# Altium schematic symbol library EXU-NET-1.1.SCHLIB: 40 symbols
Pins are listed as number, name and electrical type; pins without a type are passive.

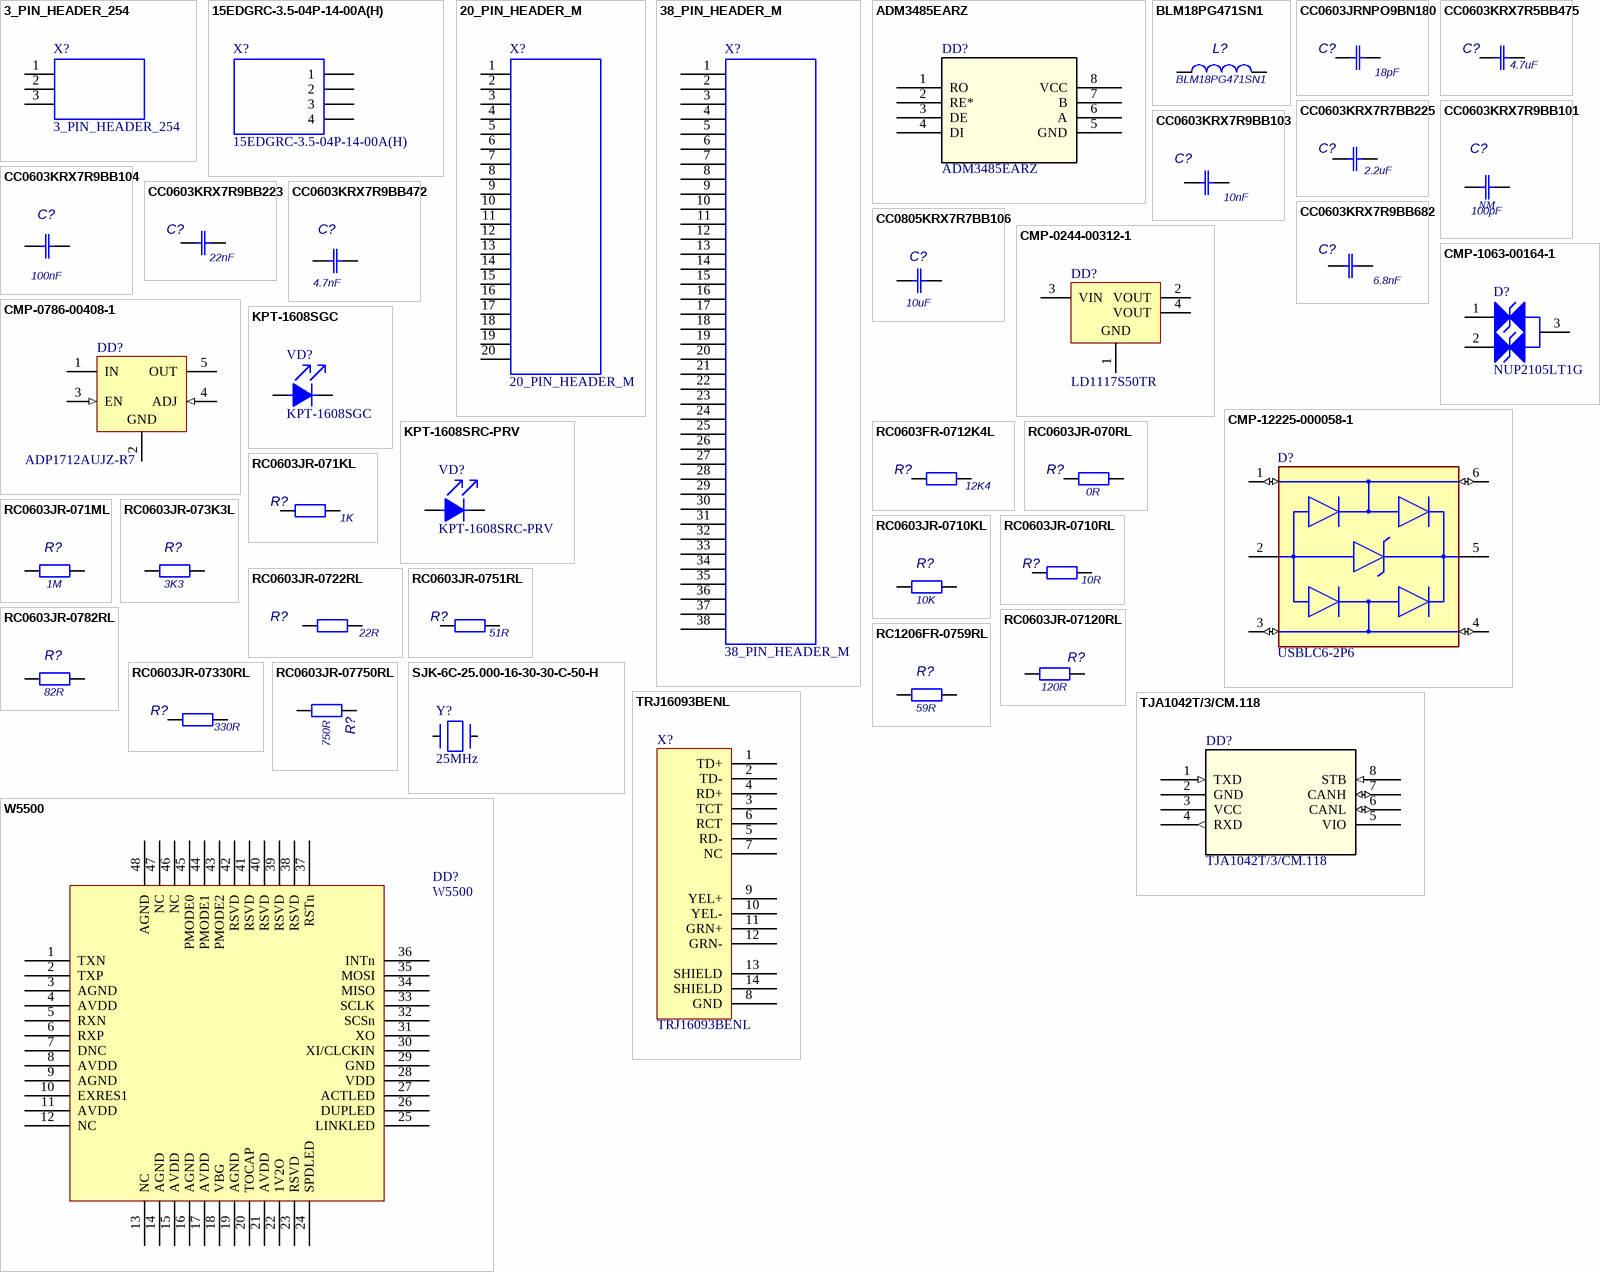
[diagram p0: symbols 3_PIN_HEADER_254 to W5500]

## 3_PIN_HEADER_254
designator X?
2,54mm Pitch, 1 Row, 3 Circuits, Vertical, THT
footprint 3_PIN_HEADER_254
pins: 1, 2, 3

## 15EDGRC-3.5-04P-14-00A(H)
designator X?
TERM BLOCK HDR 4POS 90DEG 3.5MM; Manufacturer: Degson Electronics
footprint 15EDGRC-3.5-04P-14-00A(H)
pins: 1, 2, 3, 4

## 20_PIN_HEADER_M
designator X?
footprint 20_PIN_HEADER_M
pins: 1, 2, 3, 4, 5, 6, 7, 8, 9, 10, 11, 12, 13, 14, 15, 16, 17, 18, 19, 20

## 38_PIN_HEADER_M
designator X?
footprint 38_PIN_HEADER_M
pins: 1, 2, 3, 4, 5, 6, 7, 8, 9, 10, 11, 12, 13, 14, 15, 16, 17, 18, 19, 20, 21, 22, 23, 24, 25, 26, 27, 28, 29, 30, 31, 32, 33, 34, 35, 36, 37, 38

## ADM3485EARZ
designator DD?
3.3 V, Â±15 kV ESD-Protected, RS-485/RS-422 Transceiver (Half Duplex, 12Mbps, DE/RE); Manufacturer: Youtai Semiconductor (UMW)
footprint TJA1042T/3/CM.118
pins: 1 RO, 2 RE*, 3 DE, 4 DI, 5 GND, 6 A, 7 B, 8 VCC (power)

## BLM18PG471SN1
designator L?
EMI Inductive Filter for Power lines 470Ohm 25% 100MHz 1A 200mOhm DCR 0603 T/R; Manufacturer: Murata
footprint I0603_INDC1608X10N
pins: 1, 2

## CC0603JRNPO9BN180
designator C?, comment 18pF
0603 18pF ±10% 50V; PartNumber: CC0603JRNPO9BN180; Manufacturer: YAGEO; ValueBOM: 18пФ ±5% 50В NP0 0603; ValueSCH: 18 50V; ModelSTEP: C:\AltiumLib\ALTIUM\MODEL\STEP\Capacitor\C0603_CAPC1608X09.Step; Designer: Pashinskiy; EOL: NO
footprint C0603_CAPC1608X09N
pins: 1, 2

## CC0603KRX7R5BB475
designator C?, comment 4.7uF
0603 4,7uF ±10% 6,3V; PartNumber: CC0603KRX7R5BB475; Manufacturer: YAGEO; ValueBOM: 4,7мкФ ±10% 6,3В X7R 0603; ValueSCH: 4,7u 6,3V; ModelSTEP: C:\AltiumLib\ALTIUM\MODEL\STEP\Capacitor\C0603_CAPC1608X09.Step; Designer: Dudarev; EOL: NO
footprint C0603_CAPC1608X09N
pins: 1, 2

## CC0603KRX7R7BB225
designator C?, comment 2.2uF
0603 2,2uF ±10% 16V; PartNumber: CC0603KRX7R7BB225; Manufacturer: YAGEO; ValueBOM: 2,2мкФ ±10%; ValueSCH: 2,2u 16V; ModelSTEP: C:\AltiumLib\ALTIUM\MODEL\STEP\Capacitor\C0603_CAPC1608X09.Step; Designer: Dudarev; EOL: NO
footprint C0603_CAPC1608X09N
pins: 1, 2

## CC0603KRX7R9BB101
designator C?, comment 100pF  DNP: NM
0603 100pF  ±10% 50V; PartNumber: CC0603KRX7R9BB101; Manufacturer: YAGEO; ValueBOM: 100пФ ±10% 50В X7R 0603; ValueSCH: 100 50V; ModelSTEP: C:\AltiumLib\ALTIUM\MODEL\STEP\Capacitor\C0603_CAPC1608X09.Step; Designer: Dudarev; EOL: NO
footprint C0603_CAPC1608X09N
pins: 1, 2

## CC0603KRX7R9BB103
designator C?, comment 10nF
0603 10nF ±10% 50V; PartNumber: CC0603KRX7R9BB103; Manufacturer: YAGEO; ValueBOM: 0,01мкФ ±10% 50В X7R 0603; ModelSTEP: C:\AltiumLib\ALTIUM\MODEL\STEP\Capacitor\C0603_CAPC1608X09.Step; Designer: Dudarev; EOL: NO
footprint C0603_CAPC1608X09N
pins: 1, 2

## CC0603KRX7R9BB104
designator C?, comment 100nF
0603 100nF ±10% 50V; PartNumber: CC0603KRX7R9BB104; Manufacturer: YAGEO; ValueBOM: 0,1мкФ ±10% 50В X7R 0603; ModelSTEP: C:\AltiumLib\ALTIUM\MODEL\STEP\Capacitor\C0603_CAPC1608X09.Step; Designer: Dudarev; EOL: NO
footprint C0603_CAPC1608X09N
pins: 1, 2

## CC0603KRX7R9BB223
designator C?, comment 22nF
0603 22nF ±10% 50V; PartNumber: CC0603KRX7R9BB223; Manufacturer: YAGEO; ValueBOM: 0,022мкФ ±10% 50В X7R 0603; ValueSCH: 0,022u 50V; ModelSTEP: C:\AltiumLib\ALTIUM\MODEL\STEP\Capacitor\C0603_CAPC1608X09.Step; Designer: Dudarev; EOL: NO
footprint C0603_CAPC1608X09N
pins: 1, 2

## CC0603KRX7R9BB472
designator C?, comment 4.7nF
0603 4,7nF ±10% 50V; PartNumber: CC0603KRX7R9BB472; Manufacturer: YAGEO; ValueBOM: 4700пФ ±10% 50В X7R 0603; ValueSCH: 4700 50V; ModelSTEP: C:\AltiumLib\ALTIUM\MODEL\STEP\Capacitor\C0603_CAPC1608X09.Step; Designer: Dudarev; EOL: NO
footprint C0603_CAPC1608X09N
pins: 1, 2

## CC0603KRX7R9BB682
designator C?, comment 6.8nF
0603 6,8nF ±10% 50V; PartNumber: CC0603KRX7R9BB682; Manufacturer: YAGEO; ValueBOM: 6800пФ ±10% 50В X7R 0603; ValueSCH: 6800 50V; ModelSTEP: C:\AltiumLib\ALTIUM\MODEL\STEP\Capacitor\C0603_CAPC1608X09.Step; Designer: Dudarev; EOL: NO
footprint C0603_CAPC1608X09N
pins: 1, 2

## CC0805KRX7R7BB106
designator C?, comment 10uF
Конденсатор керамический (MLCC) общего назначения 0805; PartNumber: CC0805KRX7R7BB106; Manufacturer: YAGEO; ValueBOM: 10мкФ ±10% 16В X7R 0805; ValueSCH: 10u 16V; ModelSTEP: C:\AltiumLib\ALTIUM\MODEL\STEP\Capacitor\C0805_CAPC2012X13.Step; Designer: Dudarev; EOL: NO
footprint C0805_CAPC2012X13N
pins: 1, 2

## CMP-0244-00312-1
designator DD?, comment LD1117S50TR
Fixed Low Drop Positive Voltage Regulator, 5V, 4-Pin SOT-223, Tape and Reel
footprint SOT-223_L (SOT223, 4-Leads, Body 6.5x3.5mm, Pitch 2.3mm, Lead Span 7mm, IPC High Density)
footprint SOT-223_N (SOT223, 4-Leads, Body 6.5x3.5mm, Pitch 2.3mm, Lead Span 7mm, IPC Medium Density)
footprint SOT-223_M (SOT223, 4-Leads, Body 6.5x3.5mm, Pitch 2.3mm, Lead Span 7mm, IPC Low Density)
pins: 1 GND (power), 2 VOUT (power), 3 VIN (power), 4 VOUT (power)

## CMP-0786-00408-1
designator DD?, comment ADP1712AUJZ-R7
300 mA, Low Dropout CMOS Linear Regulator, 2.5 to 5.5 V Vin, 0.8 to 5 V Vout, Industrial, 5-pin SOT23 (UJ-5), Reel; Manufacturer: Analog Devices; Vin (min) (V): 2.5; Supply Current IGND @ Small Load: 60uA; Vin (max) (V): 5.5; Iout max: 300mA; Vout Adjustable Range: 0.8V to 5V
footprint ADI-UJ-5_M (SOT23, 5-Leads, Body 2.9x1.6mm, Pitch 0.95mm, IPC Low Density)
footprint ADI-UJ-5_N (SOT23, 5-Leads, Body 2.9x1.6mm, Pitch 0.95mm, IPC Medium Density)
footprint ADI-UJ-5_L (SOT23, 5-Leads, Body 2.9x1.6mm, Pitch 0.95mm, IPC High Density)
pins: 1 IN (power) "Regulator Input Supply. Bypass IN to GND with a 2.2 uF or greater capacitor.", 2 GND (power) "Ground.", 3 EN (in) "Enable Input. Drive EN high to turn on the regulator; drive it low to turn off the regulator. For automatic startup, connect EN to IN.", 4 ADJ (in) "Adjust. A resistor divider from OUT to ADJ sets the output voltage.", 5 OUT (power) "Regulated Output Voltage. Bypass OUT to GND with a 2.2 uF or greater capacitor."

## CMP-1063-00164-1
designator D?, comment NUP2105LT1G
Dual Line CAN Bus Protector, 3-Pin SOT-23, Pb-Free, Tape and Reel; Manufacturer: On Semiconductor; IR Max (uA): 0.1; Number of Lines: 2; Direction: Bidirectional; C Max (pF): 30; PPK Max (W): 350; V(BR) Min (V): 26.2
footprint ONSC-SOT-23-3-318-08_V (SOT23, 3-Leads, Body 2.92x1.3mm, Pitch 0.95mm)
pins: 1 K, 2 K, 3 K

## CMP-12225-000058-1
designator D?, comment USBLC6-2P6
TVS DIODE 5.25V 17V SOT666; Min Breakdown Voltage: 6V; Power Line Protection: Yes; Element Configuration: Dual; Test Current: 1mA; Working Voltage: 5V; Number of Channels: 2; Max Reverse Leakage Current: 150nA; Direction: Unidirectional; Peak Pulse Current: 5A; Number of Elements: 1; Capacitance: 3.5pF
footprint FP-SOT-666-MFG
pins: 1 I/O1 (io), 2 GND (power), 3 I/O2 (io), 4 I/O2 (io), 5 VBUS (power), 6 I/O1 (io)

## KPT-1608SGC
designator VD?
Green LED SMD 0603
footprint light diode 0603
pins: 1, 2

## KPT-1608SRC-PRV
designator VD?
Red LED SMD 0603
footprint light diode 0603
pins: 1, 2

## RC0603FR-0712K4L
designator R?, comment 12K4
0603 12,4 kOhm±1% 0,1W; PartNumber: RC0603FR-0712K4L; Manufacturer: YAGEO; ValueBOM: 12,4кОм   75В 150ppm 0603; ValueSCH: 12,4K; ModelSTEP: C:\AltiumLib\ALTIUM\MODEL\STEP\Resistor\R0603_RESC1005X04.step; Designer: Dudarev; EOL: NO
footprint R0603_RESC1608X06N
pins: 1, 2

## RC0603JR-070RL
designator R?, comment 0R
0603 0 Ohm 0,1W; PartNumber: RC0603JR-070RL; Manufacturer: YAGEO; ValueBOM: 0Ом   75В 300ppm 0603; ModelSTEP: C:\AltiumLib\ALTIUM\MODEL\STEP\Resistor\R0603_RESC1005X04.step; Designer: Dudarev; EOL: NO
footprint R0603_RESC1608X06N
pins: 1, 2

## RC0603JR-071KL
designator R?, comment 1K
0603 1 kOhm±5% 0,1W; PartNumber: RC0603JR-071KL; Manufacturer: YAGEO; ValueBOM: 1кОм   75В 150ppm 0603; ModelSTEP: C:\AltiumLib\ALTIUM\MODEL\STEP\Resistor\R0603_RESC1005X04.step; Designer: Dudarev; EOL: NO
footprint R0603_RESC1608X06N
pins: 1, 2

## RC0603JR-071ML
designator R?, comment 1M
0603 1 MOhm±5% 0,1W; PartNumber: RC0603JR-071ML; Manufacturer: YAGEO; ValueBOM: 1МОм   75В 150ppm 0603; ModelSTEP: C:\AltiumLib\ALTIUM\MODEL\STEP\Resistor\R0603_RESC1005X04.step; Designer: Dudarev; EOL: NO
footprint R0603_RESC1608X06N
pins: 1, 2

## RC0603JR-073K3L
designator R?, comment 3K3
0603 3,3 kOhm±5% 0,1W; PartNumber: RC0603JR-073K3L; Manufacturer: YAGEO; ValueBOM: 3,3кОм   75В 150ppm 0603; ValueSCH: 3,3K; ModelSTEP: C:\AltiumLib\ALTIUM\MODEL\STEP\Resistor\R0603_RESC1005X04.step; Designer: Dudarev; EOL: NO
footprint R0603_RESC1608X06N
pins: 1, 2

## RC0603JR-0710KL
designator R?, comment 10K
0603 10 kOhm±5% 0,1W; PartNumber: RC0603JR-0710KL; Manufacturer: YAGEO; ValueBOM: 10кОм   75В 150ppm 0603; ModelSTEP: C:\AltiumLib\ALTIUM\MODEL\STEP\Resistor\R0603_RESC1005X04.step; Designer: Dudarev; EOL: NO
footprint R0603_RESC1608X06N
pins: 1, 2

## RC0603JR-0710RL
designator R?, comment 10R
0603 10 Ohm±5% 0,1W; PartNumber: RC0603JR-0710RL; Manufacturer: YAGEO; ValueBOM: 10Ом   75В 300ppm 0603; ModelSTEP: C:\AltiumLib\ALTIUM\MODEL\STEP\Resistor\R0603_RESC1005X04.step; Designer: Dudarev; EOL: NO
footprint R0603_RESC1608X06N
pins: 1, 2

## RC0603JR-0722RL
designator R?, comment 22R
0603 22 Ohm±5% 0,1W; PartNumber: RC0603JR-0722RL; Manufacturer: YAGEO; ValueBOM: 22Ом   75В 200ppm 0603; ModelSTEP: C:\AltiumLib\ALTIUM\MODEL\STEP\Resistor\R0603_RESC1005X04.step; Designer: Dudarev; EOL: NO
footprint R0603_RESC1608X06N
pins: 1, 2

## RC0603JR-0751RL
designator R?, comment 51R
0603 51 Ohm±5% 0,1W; PartNumber: RC0603JR-0751RL; Manufacturer: YAGEO; ValueBOM: 51Ом   75В 200ppm 0603; ModelSTEP: C:\AltiumLib\ALTIUM\MODEL\STEP\Resistor\R0603_RESC1005X04.step; Designer: Dudarev; EOL: NO
footprint R0603_RESC1608X06N
pins: 1, 2

## RC0603JR-0782RL
designator R?, comment 82R
0603 82 Ohm±5% 0,1W; PartNumber: RC0603JR-0782RL; Manufacturer: YAGEO; ValueBOM: 82Ом   75В 200ppm 0603; ModelSTEP: C:\AltiumLib\ALTIUM\MODEL\STEP\Resistor\R0603_RESC1005X04.step; Designer: Dudarev; EOL: NO
footprint R0603_RESC1608X06N
pins: 1, 2

## RC0603JR-07120RL
designator R?, comment 120R
0603 120 Ohm±5% 0,1W; PartNumber: RC0603JR-07120RL; Manufacturer: YAGEO; ValueBOM: 120Ом   75В 150ppm 0603; ModelSTEP: C:\AltiumLib\ALTIUM\MODEL\STEP\Resistor\R0603_RESC1005X04.step; Designer: Dudarev; EOL: NO
footprint R0603_RESC1608X06N
pins: 1, 2

## RC0603JR-07330RL
designator R?, comment 330R
0603 330 Ohm±5% 0,1W; PartNumber: RC0603JR-07330RL; Manufacturer: YAGEO; ValueBOM: 330Ом   75В 150ppm 0603; ModelSTEP: C:\AltiumLib\ALTIUM\MODEL\STEP\Resistor\R0603_RESC1005X04.step; Designer: Dudarev; EOL: NO
footprint R0603_RESC1608X06N
pins: 1, 2

## RC0603JR-07750RL
designator R?, comment 750R
0603 750 Ohm±5% 0,1W; PartNumber: RC0603JR-07750RL; Manufacturer: YAGEO; ValueBOM: 750Ом   75В 150ppm 0603; ModelSTEP: C:\AltiumLib\ALTIUM\MODEL\STEP\Resistor\R0603_RESC1005X04.step; Designer: Dudarev; EOL: NO
footprint R0603_RESC1608X06N
pins: 1, 2

## RC1206FR-0759RL
designator R?, comment 59R
1206 59 Ohm±1% 0,1W; PartNumber: RC1206FR-0759RL; Manufacturer: YAGEO; ValueBOM: 59Ом 1% 200В 100ppm 1206; ValueSCH: 59 1%; ModelSTEP: C:\AltiumLib\ALTIUM\MODEL\STEP\Resistor\R1206_RESC3116X07.step; Designer: Dudarev; EOL: NO
footprint R1206_RESC3116X07N
pins: 1, 2

## SJK-6C-25.000-16-30-30-C-50-H
designator Y?, comment 25MHz
25.000Мгц, HC-49SM; PartNumber: SJK-6C-25.000-16-30-30-C-50-H
footprint SJK-6C-25.000-16-30-30-C-50-H
pins: 1, 2

## TJA1042T/3/CM.118
designator DD?
Can interface, SOIC8; Manufacturer: NXP Semiconductor
footprint TJA1042T/3/CM.118
pins: 1 TXD (in), 2 GND (power), 3 VCC (power), 4 RXD (out), 5 VIO (power), 6 CANL (io), 7 CANH (io), 8 STB (in)

## TRJ16093BENL
designator X?
Connector ecr. "socket" RJ-45 C matching. 10/100Base-TX filter (1:1), 2 tops. the LED. (left green/right yellow), without petals, -40 to + 85 °C, etc. angle per board, Lc = 21.5 mm
footprint TRJ16093BENL
pins: 1 TD+, 2 TD-, 3 TCT, 4 RD+, 5 RD-, 6 RCT, 7 NC, 8 GND, 9 YEL+, 10 YEL-, 11 GRN+, 12 GRN-, 13 SHIELD, 14 SHIELD

## W5500
designator DD?
W5500, TCP/IP Ethernet Controller IC, [LQFP-48]
footprint W5500
pins: 1 TXN, 2 TXP, 3 AGND, 4 AVDD, 5 RXN, 6 RXP, 7 DNC, 8 AVDD, 9 AGND, 10 EXRES1, 11 AVDD, 12 NC, 13 NC, 14 AGND, 15 AVDD, 16 AGND, 17 AVDD, 18 VBG, 19 AGND, 20 TOCAP, 21 AVDD, 22 1V2O, 23 RSVD, 24 SPDLED, 25 LINKLED, 26 DUPLED, 27 ACTLED, 28 VDD, 29 GND, 30 XI/CLCKIN, 31 XO, 32 SCSn, 33 SCLK, 34 MISO, 35 MOSI, 36 INTn, 37 RSTn, 38 RSVD, 39 RSVD, 40 RSVD, 41 RSVD, 42 RSVD, 43 PMODE2, 44 PMODE1, 45 PMODE0, 46 NC, 47 NC, 48 AGND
